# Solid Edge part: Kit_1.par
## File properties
Sűrűség: 0,000 kg/m^3
Pontosság: 0,990
Author: ahadarics
Last saved by: ahadarics
Revision: 77
Username: ahadarics
Dokumentum tartalom típus: 0
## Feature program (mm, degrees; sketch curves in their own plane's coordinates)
base feature "unnamed BaseFeature 1"
sketch for "Furat_1" plane through (17.5, -62.25, 0) normal (1, 0, 0) x-axis (0, 1, 0)
  hole centre (0, 0) bore radius 3.4585
hole "Furat_1" nominal diameter 8 finite  ThreadDepth = 6.5 mm
sketch for "Furat_2" plane through (-17.5, -62.25, 0) normal (-1, 0, 0) x-axis (0, -1, 0)
  hole centre (0, 0) bore radius 3.4585
hole "Furat_2" nominal diameter 8 finite  ThreadDepth = 6.5 mm
thread "unnamed Thread 1"
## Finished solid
Body 1: solid body, 61 faces, 63 edges, 4 vertices, 1 internal void.
  Faces by surface: plane 22, cylinder 21, cone 13, torus 5
  Edges by curve: circle 56, line 4, intersection 3
Bounding box of the edges (mm; curved faces can reach further): 38.000 x 54.000 x 36.500, from (-19, -101.25, -19) to (19, -47.25, 17.5).
Cylindrical faces by radius (mm): R1.5 x1, R3.455 x2, R3.4585 x2, R5 x2, R6.4 x1, R6.4236 x1, R6.5 x2, R9 x1, R11 x3, R14 x2, R15 x2, R16.8 x1, R19 x1
Conical faces (half-angle, radius in mm at the cone's reference point): 1.6538 deg R7.75 x1, 3.5477 deg R8.7454 x1, 5.762 deg R6.4 x1, 11.1239 deg R6.0056 x1, 15.3654 deg R6.7214 x1, 19.3654 deg R7.1921 x1, 25.0169 deg R10.31 x1, 30 deg R9.2887 x1, 30 deg R11.4263 x1, 30 deg R11.5774 x1, 36.3268 deg R11 x1, 45 deg R1.6 x1, 45 deg R13.75 x1
Toroidal faces (ring radius, tube radius in mm): R6.3 r0.3 x1, R6.3085 r0.3 x1, R7.4279 r0.25 x1, R8.2464 r0.5 x1, R10.8 r0.2 x1
Planar faces by outward normal: +x 3, +y 6, +z 1, -x 3, -y 9
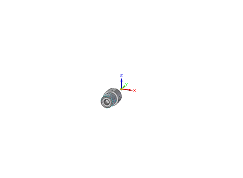
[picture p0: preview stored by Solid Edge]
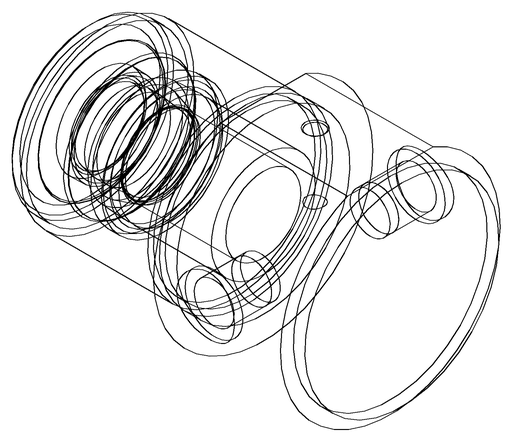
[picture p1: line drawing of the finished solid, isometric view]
